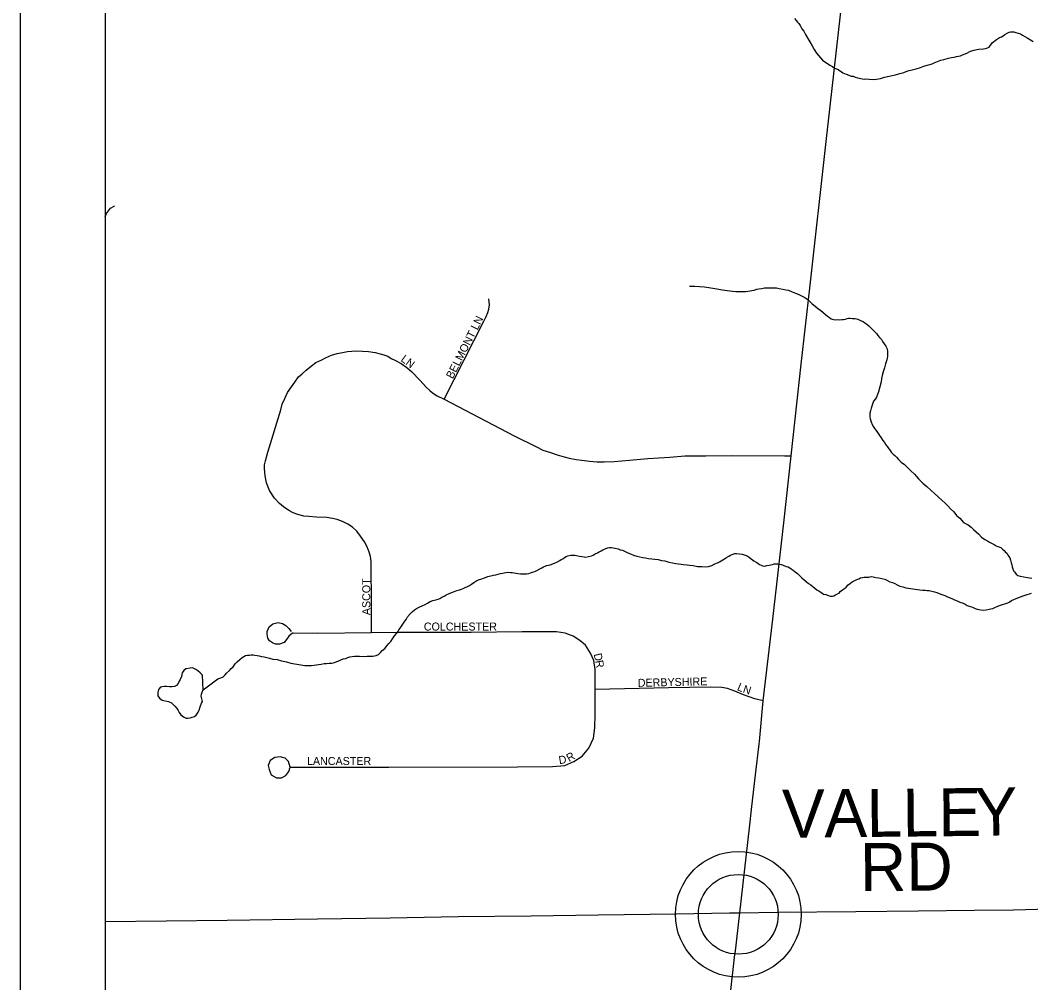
# Model space of a CAD drawing. Extents: x 10.6 to 44.6, y -2.6 to 23.4.
# Drawn here: x 13.103 to 14.299, y 18.108 to 19.247 of the extents above; entities that cross this region are included whole.
import ezdxf

# ---------------------------------------------------------------- set-up
doc = ezdxf.new("R2010")
doc.units = 0
for name, color, linetype in [('GM_X_County', 7, 'Continuous'), ('GM_X_County_Road', 7, 'Continuous'), ('GM_X_Minor_Lake', 7, 'Continuous'), ('GM_X_Minor_River', 7, 'Continuous'), ('GM_X_State_Route', 7, 'Continuous'), ('GM_X_Township', 7, 'Continuous'), ('GM_X_Township_Road', 7, 'Continuous'), ('GM_X_Township_Road_Text', 7, 'Continuous'), ('GM_X_Township_Subdivision', 7, 'Continuous'), ('GM_X_Township_Subdivision_Text', 7, 'Continuous'), ('GM_X_Unincorporated', 7, 'Continuous'), ('SH_Data', 7, 'Continuous')]:
    doc.layers.add(name, color=color, linetype=linetype)

msp = doc.modelspace()

# ---------------------------------------------------------------- linework, layer by layer
at = {"layer": 'GM_X_County'}
msp.add_lwpolyline([(20.0033, 15.5302), (20.0033, 22.3267), (13.2033, 22.3267), (13.2033, 15.5267), (19.8413, 15.5267)], dxfattribs=at)
at = {"layer": 'GM_X_County_Road'}
msp.add_lwpolyline([(13.2033, 18.1804), (13.3479, 18.1819), (13.4545, 18.1834), (13.5408, 18.1846), (13.6212, 18.1861), (13.7077, 18.1871), (13.7867, 18.1883), (13.8793, 18.1893), (13.9421, 18.1903), (13.9546, 18.1903)], dxfattribs=at)
at = {"layer": 'GM_X_Minor_Lake'}
for points in [[(13.3185, 18.4717), (13.3158, 18.4747), (13.3131, 18.4769), (13.3108, 18.4784), (13.3089, 18.4795), (13.3069, 18.4806), (13.3039, 18.4801), (13.299, 18.4793), (13.2964, 18.4773), (13.2945, 18.4746), (13.2935, 18.4704), (13.292, 18.4666), (13.2909, 18.4647), (13.2898, 18.462), (13.2876, 18.4597), (13.2853, 18.4585), (13.2823, 18.458), (13.2793, 18.458), (13.2758, 18.4583), (13.2735, 18.4586), (13.2709, 18.4581), (13.269, 18.4577), (13.2664, 18.455), (13.2657, 18.4512), (13.2658, 18.4474), (13.2678, 18.4448), (13.2709, 18.4422)], [(13.3185, 18.4717), (13.3158, 18.4747), (13.3131, 18.4769), (13.3108, 18.4784), (13.3089, 18.4795), (13.3069, 18.4806), (13.3039, 18.4801), (13.299, 18.4793), (13.2964, 18.4773), (13.2945, 18.4746), (13.2935, 18.4704), (13.292, 18.4666), (13.2909, 18.4647), (13.2898, 18.462), (13.2876, 18.4597), (13.2853, 18.4585), (13.2823, 18.458), (13.2793, 18.458), (13.2758, 18.4583), (13.2735, 18.4586), (13.2709, 18.4581), (13.269, 18.4577), (13.2664, 18.455), (13.2657, 18.4512), (13.2658, 18.4474), (13.2678, 18.4448), (13.2709, 18.4422), (13.2785, 18.4408), (13.282, 18.439), (13.2839, 18.4371), (13.2858, 18.4353), (13.2886, 18.4319), (13.2898, 18.4301), (13.2909, 18.4278), (13.2929, 18.4248), (13.296, 18.4226), (13.2991, 18.4211), (13.301, 18.4208), (13.304, 18.4212), (13.3063, 18.4221), (13.3089, 18.4229), (13.3112, 18.4244), (13.3134, 18.4279), (13.3145, 18.4306), (13.3159, 18.4344), (13.3173, 18.4386), (13.3184, 18.4406), (13.3176, 18.444), (13.3168, 18.447), (13.3175, 18.4493), (13.3186, 18.4531), (13.3193, 18.4546), (13.3185, 18.4717)], [(13.2709, 18.4422), (13.2785, 18.4408), (13.282, 18.439), (13.2839, 18.4371), (13.2858, 18.4353), (13.2886, 18.4319), (13.2898, 18.4301), (13.2909, 18.4278), (13.2929, 18.4248), (13.296, 18.4226), (13.2991, 18.4211), (13.301, 18.4208), (13.304, 18.4212), (13.3063, 18.4221), (13.3089, 18.4229), (13.3112, 18.4244), (13.3134, 18.4279), (13.3145, 18.4306), (13.3159, 18.4344), (13.3173, 18.4386), (13.3184, 18.4406), (13.3176, 18.444), (13.3168, 18.447), (13.3175, 18.4493), (13.3186, 18.4531), (13.3193, 18.4546), (13.3185, 18.4717)]]:
    msp.add_lwpolyline(points, dxfattribs=at)
at = {"layer": 'GM_X_Minor_River'}
for points in [[(14.019, 19.2493), (14.021, 19.2471), (14.0229, 19.2452), (14.0245, 19.2433), (14.0261, 19.2411), (14.0277, 19.2373), (14.0304, 19.2343), (14.0324, 19.2306), (14.0351, 19.2257), (14.0375, 19.2216), (14.0403, 19.2171), (14.0426, 19.2126), (14.0454, 19.2084), (14.0477, 19.2055), (14.0501, 19.2028), (14.0524, 19.2002)], [(14.0524, 19.2002), (14.0609, 19.1943), (14.064, 19.1925), (14.0667, 19.1907), (14.0701, 19.1892), (14.0732, 19.1874), (14.0763, 19.1852), (14.0802, 19.1834), (14.0836, 19.1823), (14.0863, 19.1812), (14.0886, 19.1809), (14.0909, 19.1798), (14.0939, 19.1791), (14.0962, 19.1788), (14.0993, 19.1781), (14.102, 19.1777), (14.1046, 19.1778), (14.1077, 19.1775), (14.1122, 19.1772), (14.1164, 19.1777), (14.121, 19.1785), (14.1259, 19.1798), (14.1312, 19.181), (14.1388, 19.1827), (14.1437, 19.1844), (14.1486, 19.1856), (14.1535, 19.1872), (14.1584, 19.1885), (14.1633, 19.1897), (14.1682, 19.1913), (14.1724, 19.193), (14.1762, 19.1942), (14.1792, 19.195), (14.1822, 19.1958), (14.1845, 19.197), (14.1886, 19.1986), (14.1924, 19.1999), (14.1958, 19.2007), (14.1988, 19.2015), (14.2015, 19.2023), (14.2049, 19.2032), (14.2083, 19.2036), (14.211, 19.2044), (14.2132, 19.2049), (14.2155, 19.2053), (14.2181, 19.2065), (14.223, 19.2085), (14.2276, 19.2105), (14.2317, 19.2117), (14.2351, 19.2126), (14.2374, 19.213), (14.2427, 19.2135), (14.2454, 19.2139), (14.2476, 19.2147), (14.2495, 19.2155), (14.2532, 19.2206), (14.2581, 19.2245), (14.2618, 19.2268), (14.2641, 19.2276), (14.266, 19.2288), (14.2682, 19.2304), (14.2709, 19.232), (14.2731, 19.2332), (14.275, 19.2336), (14.2788, 19.2337), (14.2811, 19.2329), (14.2838, 19.2319), (14.2865, 19.2312), (14.2892, 19.2297), (14.2919, 19.2282), (14.2946, 19.2264), (14.2984, 19.2242), (14.3015, 19.222)], [(13.2033, 19.0147), (13.2049, 19.0184), (13.2098, 19.0246), (13.2139, 19.0273), (13.2143, 19.0274)], [(13.8949, 18.9323), (13.8976, 18.9324), (13.9014, 18.9324), (13.9067, 18.9322), (13.9128, 18.9316), (13.9201, 18.9306), (13.9273, 18.9292), (13.9338, 18.9282), (13.9395, 18.9272), (13.946, 18.9266), (13.9498, 18.9263), (13.9529, 18.926), (13.9559, 18.926), (13.9586, 18.9261), (13.9616, 18.9262), (13.9639, 18.9266), (13.9666, 18.927), (13.9688, 18.9275), (13.9715, 18.9279), (13.9745, 18.9287), (13.9768, 18.9291), (13.9806, 18.9296), (13.9836, 18.9304), (13.9866, 18.9305), (13.9885, 18.9305), (13.9908, 18.9306), (13.9939, 18.9303), (13.9977, 18.9304), (14.0011, 18.9297), (14.0053, 18.929), (14.0091, 18.9283), (14.0122, 18.9276), (14.0164, 18.9258), (14.0203, 18.924), (14.0237, 18.9229), (14.0268, 18.9215), (14.0291, 18.9204), (14.0314, 18.9189), (14.0337, 18.9175), (14.0356, 18.916), (14.0376, 18.9137), (14.0403, 18.9115), (14.0434, 18.9093), (14.0465, 18.9063), (14.0504, 18.9038), (14.0581, 18.8971), (14.0608, 18.8952), (14.0627, 18.8938), (14.0654, 18.8931), (14.0673, 18.8927), (14.0696, 18.8928), (14.0719, 18.8924), (14.0753, 18.8929), (14.0772, 18.8929), (14.0795, 18.8934), (14.0814, 18.8942), (14.0833, 18.8946), (14.0852, 18.8946), (14.0875, 18.8943), (14.0909, 18.894), (14.0943, 18.8933), (14.0974, 18.8919), (14.1005, 18.8908), (14.1024, 18.8889), (14.1047, 18.8875), (14.107, 18.8856), (14.109, 18.8834), (14.1113, 18.8815), (14.1144, 18.8782), (14.1164, 18.8763), (14.1179, 18.8741), (14.1199, 18.8718), (14.1222, 18.8692), (14.1234, 18.867), (14.1254, 18.8643), (14.1273, 18.8613), (14.1285, 18.8591), (14.1294, 18.8557), (14.1294, 18.853), (14.1291, 18.8492), (14.1284, 18.8454), (14.127, 18.8404), (14.1256, 18.8358), (14.1242, 18.8309), (14.1231, 18.8267), (14.1221, 18.8232), (14.1218, 18.819), (14.1186, 18.8072), (14.1175, 18.8041), (14.1161, 18.8011), (14.115, 18.7991), (14.1127, 18.7964), (14.112, 18.7941), (14.111, 18.7914), (14.1099, 18.788), (14.1092, 18.7849), (14.1085, 18.7819), (14.1082, 18.7796), (14.1082, 18.7777), (14.1086, 18.7754), (14.1098, 18.772)], [(14.1098, 18.772), (14.1111, 18.7686), (14.1126, 18.766), (14.1138, 18.7641), (14.1158, 18.7615), (14.1181, 18.7582), (14.1197, 18.7555), (14.1217, 18.7529), (14.1236, 18.7499), (14.1256, 18.7473), (14.1272, 18.7447), (14.1291, 18.7421), (14.1307, 18.7398), (14.1323, 18.7379), (14.1338, 18.7361), (14.1358, 18.7335), (14.1381, 18.732), (14.14, 18.7298), (14.1424, 18.7271), (14.1455, 18.7242), (14.1493, 18.7212), (14.1528, 18.7179), (14.1567, 18.7138), (14.1614, 18.7097), (14.1661, 18.7045), (14.1711, 18.6993), (14.1758, 18.6952), (14.1808, 18.6904), (14.1843, 18.6874), (14.194, 18.6785), (14.1975, 18.6755), (14.2006, 18.6725), (14.2037, 18.6688), (14.2076, 18.6651), (14.2111, 18.661), (14.215, 18.6577), (14.2193, 18.6528), (14.2247, 18.6499), (14.2281, 18.6473), (14.2312, 18.6443), (14.2343, 18.6417), (14.2375, 18.6388), (14.2406, 18.6354), (14.2444, 18.6324), (14.2475, 18.631), (14.2498, 18.6295), (14.2533, 18.6277), (14.2556, 18.6266), (14.2579, 18.6251), (14.2598, 18.6244), (14.2633, 18.623), (14.2652, 18.6211), (14.2672, 18.6196), (14.2687, 18.6178), (14.2707, 18.6159), (14.2718, 18.614), (14.2742, 18.6107), (14.275, 18.608), (14.2758, 18.605), (14.2763, 18.6024), (14.2767, 18.6001), (14.2783, 18.5956), (14.2799, 18.5937), (14.2814, 18.5914), (14.2834, 18.59), (14.2864, 18.5889), (14.2948, 18.5876), (14.2975, 18.5872), (14.3002, 18.5869)], [(13.6196, 18.5721), (13.6226, 18.573), (13.6249, 18.5738), (13.6271, 18.5746), (13.6294, 18.5758), (13.632, 18.577), (13.6347, 18.5782), (13.6369, 18.5797), (13.6395, 18.5817), (13.6422, 18.5833), (13.6452, 18.5848), (13.649, 18.5861), (13.6512, 18.5869), (13.6535, 18.5877), (13.6561, 18.5885), (13.658, 18.5889), (13.6599, 18.5893), (13.6629, 18.5902), (13.6656, 18.5906), (13.6713, 18.5923), (13.6735, 18.5927), (13.6754, 18.5931), (13.6777, 18.5935), (13.6811, 18.594), (13.683, 18.5936), (13.6849, 18.5933), (13.6876, 18.593), (13.6899, 18.5927), (13.6918, 18.5923), (13.6949, 18.592), (13.6971, 18.5917), (13.6998, 18.5917), (13.7025, 18.5918), (13.7047, 18.5922), (13.7066, 18.593), (13.7093, 18.5938), (13.7119, 18.5947), (13.7142, 18.5958), (13.7179, 18.5978), (13.7202, 18.599), (13.7221, 18.6002), (13.724, 18.601), (13.7258, 18.6018), (13.7281, 18.6022), (13.73, 18.6027), (13.733, 18.6035), (13.736, 18.6047), (13.7379, 18.6055), (13.7413, 18.6078), (13.7432, 18.609), (13.7451, 18.6098), (13.7469, 18.611), (13.7488, 18.6122), (13.7511, 18.613), (13.7545, 18.6138), (13.7568, 18.6139), (13.7591, 18.6139), (13.7613, 18.6136), (13.7648, 18.6129), (13.7675, 18.6122), (13.7701, 18.6119), (13.772, 18.6115), (13.7789, 18.6132), (13.7811, 18.614), (13.7834, 18.6156), (13.786, 18.6168), (13.7879, 18.618), (13.7905, 18.6192), (13.7924, 18.6203), (13.7958, 18.6219), (13.7984, 18.6228), (13.8003, 18.6232), (13.8026, 18.6229), (13.8045, 18.6225), (13.8068, 18.6222), (13.8106, 18.6215), (13.8129, 18.6204), (13.8156, 18.6197), (13.8187, 18.6183), (13.8218, 18.6168), (13.8252, 18.6157), (13.8287, 18.6139), (13.8325, 18.6129), (13.8363, 18.6118), (13.8398, 18.6111), (13.8428, 18.6108), (13.8463, 18.6101), (13.8504, 18.6098), (13.8539, 18.6091), (13.8577, 18.6088), (13.8619, 18.6078), (13.8657, 18.6071), (13.8703, 18.6057), (13.8749, 18.6047), (13.8787, 18.604), (13.8821, 18.6037), (13.8852, 18.6034), (13.8879, 18.603), (13.8921, 18.6024), (13.8951, 18.6021), (13.8993, 18.6018)], [(13.8993, 18.6018), (13.9043, 18.6007), (13.9096, 18.6005), (13.9142, 18.6002), (13.9176, 18.6006), (13.9214, 18.6019), (13.9251, 18.6035), (13.9282, 18.6047), (13.9304, 18.6059), (13.9364, 18.6098), (13.9387, 18.611), (13.9413, 18.6129), (13.9435, 18.6141), (13.9454, 18.6149), (13.9485, 18.6158), (13.9504, 18.6158), (13.9542, 18.6155), (13.9572, 18.6152), (13.961, 18.6141), (13.963, 18.613), (13.9657, 18.6116), (13.968, 18.6097), (13.9711, 18.6071), (13.9738, 18.6057), (13.9757, 18.6046), (13.9776, 18.6031), (13.9796, 18.602), (13.9815, 18.6013), (13.9842, 18.601), (13.9864, 18.6018), (13.9891, 18.6022), (13.9913, 18.6026), (13.9932, 18.603), (13.9951, 18.6035), (13.997, 18.6035), (13.9993, 18.6036), (14.0012, 18.6032), (14.0035, 18.6029), (14.0058, 18.6022), (14.0093, 18.6007), (14.0116, 18.6), (14.0135, 18.5989), (14.0154, 18.5978), (14.0177, 18.596), (14.0201, 18.5941), (14.0228, 18.5923), (14.0251, 18.5897), (14.0278, 18.5871), (14.0305, 18.5849), (14.0332, 18.5826), (14.0356, 18.5804), (14.0386, 18.579), (14.041, 18.5767), (14.0433, 18.5749), (14.0456, 18.573), (14.0479, 18.5716), (14.0518, 18.569), (14.0537, 18.5679), (14.0564, 18.5672), (14.0595, 18.5661), (14.0614, 18.5654), (14.064, 18.5654), (14.0659, 18.5659), (14.0678, 18.567), (14.0701, 18.5682), (14.0719, 18.569), (14.0734, 18.571), (14.076, 18.5729), (14.0783, 18.5745), (14.0802, 18.5761), (14.0828, 18.5788), (14.0854, 18.5807), (14.0876, 18.5823), (14.0906, 18.5839), (14.0929, 18.5851), (14.0952, 18.5859), (14.0974, 18.5871), (14.0997, 18.5875), (14.1016, 18.5879), (14.105, 18.588), (14.1073, 18.588), (14.1099, 18.5885), (14.1122, 18.5882), (14.1153, 18.5875), (14.1191, 18.5872), (14.1225, 18.5865), (14.126, 18.5854), (14.1291, 18.584), (14.1321, 18.5825), (14.1352, 18.5814), (14.1379, 18.5803), (14.1406, 18.5789), (14.144, 18.5774), (14.1475, 18.5764), (14.1509, 18.5753), (14.1593, 18.574), (14.162, 18.5737), (14.1647, 18.5733), (14.1677, 18.573), (14.1711, 18.5727), (14.1738, 18.5724)], [(13.3193, 18.4546), (13.3365, 18.4676), (13.3403, 18.4688), (13.3429, 18.47), (13.3452, 18.4723), (13.347, 18.4742), (13.3504, 18.4774), (13.3526, 18.4797), (13.3548, 18.4816), (13.3571, 18.4851), (13.3597, 18.4878), (13.3626, 18.4905), (13.3653, 18.4929), (13.3675, 18.4941), (13.3694, 18.4953), (13.3717, 18.4957), (13.3743, 18.4957), (13.3762, 18.4958), (13.3785, 18.4958), (13.3804, 18.4955), (13.3831, 18.4952), (13.3858, 18.4948), (13.3884, 18.4941), (13.3915, 18.4935), (13.3945, 18.4928), (13.398, 18.4921), (13.4018, 18.491), (13.4068, 18.4904), (13.4121, 18.489), (13.4179, 18.4876), (13.4232, 18.4862), (13.4396, 18.4835), (13.4442, 18.4832), (13.4476, 18.4833), (13.4507, 18.4837), (13.4533, 18.4842), (13.456, 18.4846), (13.459, 18.485), (13.4624, 18.4855), (13.4655, 18.4856), (13.4685, 18.486), (13.4715, 18.4861), (13.4749, 18.4869), (13.4776, 18.4881), (13.4798, 18.4889), (13.4821, 18.4901), (13.4851, 18.4913), (13.4881, 18.4918), (13.4904, 18.4926), (13.4931, 18.4934), (13.4957, 18.4938), (13.4984, 18.4943), (13.501, 18.4943), (13.5045, 18.4944), (13.5098, 18.4941), (13.5136, 18.4942), (13.517, 18.4943), (13.52, 18.4943), (13.5223, 18.4948), (13.5242, 18.4952), (13.5269, 18.4964), (13.5291, 18.4987), (13.5313, 18.501), (13.5343, 18.5034), (13.5373, 18.5069), (13.5391, 18.5092), (13.5414, 18.5119), (13.5436, 18.515), (13.5458, 18.5185), (13.548, 18.5212), (13.5499, 18.5231), (13.551, 18.5254), (13.5524, 18.5277), (13.5539, 18.53), (13.5558, 18.5324), (13.558, 18.5358), (13.5594, 18.5378), (13.5613, 18.5408), (13.5643, 18.5443), (13.5665, 18.547), (13.5695, 18.5494), (13.5717, 18.551), (13.574, 18.5518), (13.5759, 18.5529), (13.5785, 18.5541), (13.5819, 18.5557), (13.5849, 18.5573), (13.5879, 18.5589), (13.5913, 18.5601), (13.5947, 18.561), (13.5974, 18.5618), (13.5996, 18.5626), (13.6019, 18.5641), (13.6045, 18.5653), (13.6071, 18.5669), (13.6105, 18.5685), (13.6158, 18.5705), (13.6196, 18.5721)], [(14.1738, 18.5724), (14.1761, 18.5721), (14.1784, 18.5721), (14.1818, 18.5714), (14.1849, 18.5707), (14.1876, 18.5696), (14.1906, 18.5686), (14.1937, 18.5675), (14.1972, 18.5661), (14.2002, 18.5646), (14.2033, 18.5635), (14.206, 18.5624), (14.2087, 18.561), (14.2117, 18.5599), (14.2148, 18.5585), (14.2187, 18.557), (14.221, 18.5559), (14.2237, 18.5545), (14.226, 18.5534), (14.2286, 18.5527), (14.2306, 18.552), (14.2329, 18.5509), (14.2352, 18.5502), (14.2374, 18.5498), (14.2397, 18.5491), (14.2432, 18.5488), (14.2462, 18.5493), (14.2496, 18.5501), (14.2515, 18.5505), (14.2538, 18.5509), (14.2572, 18.5522), (14.2591, 18.553), (14.2617, 18.5542), (14.2643, 18.555), (14.2666, 18.5558), (14.2693, 18.5566), (14.2715, 18.5574), (14.2734, 18.5582), (14.276, 18.5602), (14.2836, 18.5634), (14.29, 18.5658), (14.2945, 18.5674), (14.2975, 18.5682), (14.2998, 18.569)]]:
    msp.add_lwpolyline(points, dxfattribs=at)
at = {"layer": 'GM_X_State_Route'}
for points in [[(13.9776, 18.3932), (13.9823, 18.4416), (13.9935, 18.5382), (14.0064, 18.6522), (14.0152, 18.7317), (14.0271, 18.84), (14.0375, 18.9302), (14.0568, 19.1037), (14.0782, 19.2961)], [(13.9546, 18.1903), (13.9659, 18.291), (13.9688, 18.3165), (13.9731, 18.354), (13.9773, 18.3902), (13.9776, 18.3932)], [(13.9488, 18.142), (13.9546, 18.1903)], [(13.9344, 18.0165), (13.9384, 18.053), (13.9423, 18.0849), (13.9487, 18.1412), (13.9488, 18.142)]]:
    msp.add_lwpolyline(points, dxfattribs=at)
at = {"layer": 'GM_X_Township'}
msp.add_lwpolyline([(13.2033, 20.8217), (13.2033, 15.5267), (15.2903, 15.5267)], dxfattribs=at)
at = {"layer": 'GM_X_Township_Road'}
msp.add_lwpolyline([(13.9546, 18.1903), (13.999, 18.1913), (14.0917, 18.1921), (14.1657, 18.193), (14.2324, 18.1938), (14.2783, 18.1941), (14.3206, 18.1952), (14.3322, 18.1953), (14.3418, 18.1959), (14.348, 18.1978), (14.356, 18.202)], dxfattribs=at)
at = {"layer": 'GM_X_Township_Subdivision'}
for points in [[(13.6044, 18.7986), (13.6514, 18.8909), (13.6541, 18.8966), (13.6563, 18.9014), (13.6575, 18.9052), (13.6582, 18.9104), (13.6575, 18.9173)], [(13.5185, 18.522), (13.5185, 18.5623), (13.5181, 18.5971), (13.518, 18.6065), (13.5173, 18.6122), (13.5159, 18.6177), (13.5135, 18.6237), (13.5104, 18.6298), (13.5056, 18.6365), (13.5011, 18.6422), (13.4961, 18.647), (13.4904, 18.6508), (13.4842, 18.6539), (13.478, 18.656), (13.4723, 18.6575), (13.4656, 18.6584), (13.4533, 18.6591), (13.4442, 18.6596), (13.4383, 18.6601), (13.4314, 18.662), (13.4259, 18.6639), (13.4209, 18.667), (13.4145, 18.671), (13.4095, 18.6753), (13.4038, 18.6815), (13.3978, 18.6905), (13.3942, 18.6996), (13.3926, 18.7077), (13.3919, 18.7165), (13.3921, 18.721), (13.3933, 18.7258), (13.3959, 18.7358), (13.4111, 18.786), (13.4128, 18.7929), (13.4159, 18.7995), (13.419, 18.8067), (13.4238, 18.8133), (13.4278, 18.8188), (13.4323, 18.825), (13.4364, 18.8288), (13.4411, 18.8329), (13.4476, 18.8381), (13.4528, 18.8419), (13.4597, 18.8452), (13.464, 18.8476), (13.4714, 18.8507), (13.478, 18.8526), (13.4842, 18.854), (13.4902, 18.855), (13.4954, 18.8555), (13.5013, 18.8557), (13.5078, 18.8555), (13.5149, 18.855), (13.523, 18.854), (13.529, 18.8524), (13.5332, 18.8512), (13.5378, 18.8495), (13.542, 18.8469), (13.5463, 18.845), (13.5535, 18.8409), (13.5604, 18.8362), (13.5663, 18.8312), (13.5756, 18.821), (13.5832, 18.8129), (13.5877, 18.8088), (13.5908, 18.8062), (13.5961, 18.8026), (13.6044, 18.7986), (13.6875, 18.7553), (13.7139, 18.7422), (13.7215, 18.7384), (13.7303, 18.7355), (13.7384, 18.7327), (13.7465, 18.7303), (13.7524, 18.7288), (13.7608, 18.7274), (13.7674, 18.7265), (13.7765, 18.7253), (13.7853, 18.7246), (13.7941, 18.7243), (13.8057, 18.725), (13.8241, 18.7265), (13.8457, 18.7284), (13.8717, 18.7298), (13.8893, 18.7317), (13.8983, 18.7317), (13.9143, 18.7317), (13.9459, 18.7319), (14.0073, 18.7317), (14.0152, 18.7317)], [(13.4258, 18.5218), (13.4252, 18.5218), (13.4207, 18.5179), (13.4181, 18.5142), (13.4152, 18.5106), (13.4095, 18.5084), (13.405, 18.5086), (13.4014, 18.5103), (13.398, 18.5127), (13.3957, 18.5156), (13.3949, 18.5206), (13.3951, 18.5234), (13.3976, 18.529), (13.4018, 18.5326), (13.408, 18.5342), (13.4133, 18.5332), (13.4172, 18.5306), (13.4209, 18.5273), (13.4233, 18.5237)], [(13.7834, 18.4549), (13.7831, 18.4785), (13.7817, 18.4892), (13.7779, 18.498), (13.7717, 18.5073), (13.7651, 18.5128), (13.7572, 18.5182), (13.7477, 18.5216), (13.7374, 18.5232), (13.6969, 18.523), (13.6365, 18.5225), (13.5489, 18.5223), (13.5185, 18.522), (13.4549, 18.5213), (13.4258, 18.5218)], [(13.9823, 18.4416), (13.9722, 18.4438), (13.9588, 18.4487), (13.9486, 18.4529), (13.9399, 18.4559), (13.9331, 18.4573), (13.9197, 18.4575), (13.87, 18.4567), (13.7834, 18.4549)], [(13.4223, 18.3628), (13.4202, 18.3697), (13.4164, 18.3738), (13.4104, 18.3752), (13.4042, 18.3742), (13.3988, 18.3709), (13.3964, 18.365), (13.3973, 18.36), (13.4, 18.354), (13.4061, 18.3504), (13.4119, 18.3504), (13.4173, 18.3531), (13.4209, 18.3578), (13.4223, 18.3628), (13.5389, 18.3631), (13.6915, 18.3635), (13.7327, 18.3638), (13.7474, 18.365), (13.7579, 18.3695), (13.7679, 18.3759), (13.7758, 18.3854), (13.7812, 18.3971), (13.7829, 18.4097), (13.7834, 18.4252), (13.7834, 18.4549)]]:
    msp.add_lwpolyline(points, dxfattribs=at)
at = {"layer": 'GM_X_Unincorporated'}
for radius in [0.0744, 0.0472]:
    msp.add_circle((13.9527, 18.1887), radius, dxfattribs=at)
at = {"layer": 'SH_Data'}
msp.add_line((13.1028, 22.4265), (13.1028, 15.4265), dxfattribs=at)

# ---------------------------------------------------------------- texts
at = {"layer": 'GM_X_Township_Road_Text'}
for s, height, rotation, p in [('V', 0.0568, 0.5319, (14.0047, 18.2794)), ('A', 0.0568, 0.5319, (14.0547, 18.2799)), ('L', 0.0568, 0.5271, (14.1047, 18.2803)), ('L', 0.0568, 0.5314, (14.1472, 18.2807)), ('E', 0.0568, 0.5314, (14.1897, 18.2811)), ('Y', 0.0568, 1.1717, (14.2329, 18.2815)), ('RD', 0.05682, 0.4936, (14.0969, 18.2161))]:
    msp.add_text(s, height=height, rotation=rotation, dxfattribs=at).set_placement(p)
at = {"layer": 'GM_X_Township_Subdivision_Text'}
for s, rotation, p in [('BELMONT LN', 63.1446, (13.6147, 18.822)), ('LN', 323.7481, (13.5524, 18.8443)), ('ASCOT', 90, (13.5171, 18.5429)), ('COLCHESTER', 0, (13.5805, 18.5247)), ('D', 282.9864, (13.7814, 18.4967)), ('R', 280.8241, (13.7832, 18.4887)), ('DERBYSHIRE', 1.3187, (13.8338, 18.458)), ('L', 336.7727, (13.9505, 18.4545)), ('N', 341.9236, (13.9574, 18.4515)), ('LANCASTER', 0, (13.4422, 18.3655)), ('D', 9.3509, (13.7409, 18.3664)), ('R', 29.7349, (13.7525, 18.3689))]:
    msp.add_text(s, height=0.00947, rotation=rotation, dxfattribs=at).set_placement(p)

doc.saveas('drawing.dxf')
